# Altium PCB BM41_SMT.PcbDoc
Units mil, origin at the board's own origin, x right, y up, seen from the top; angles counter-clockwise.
Board outline 6000 x 4000 mil, 2 copper layers (Top, Bottom), stack 12.7 mil thick; 2 components, 0 nets, 32 pads, 0 vias.
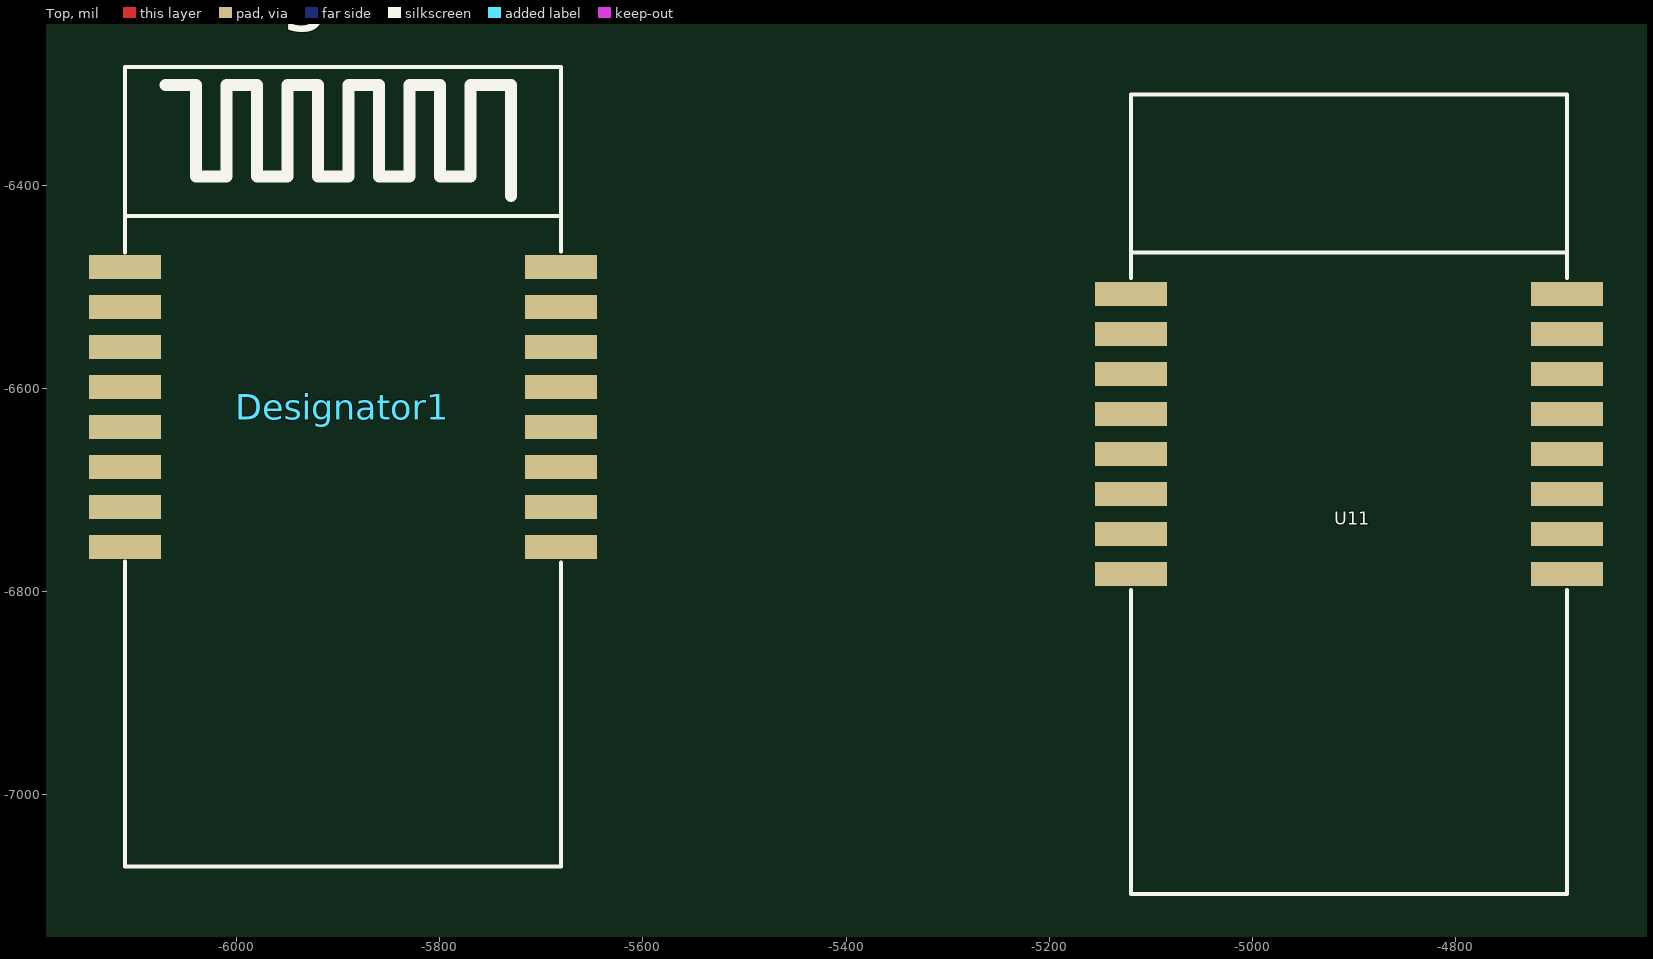
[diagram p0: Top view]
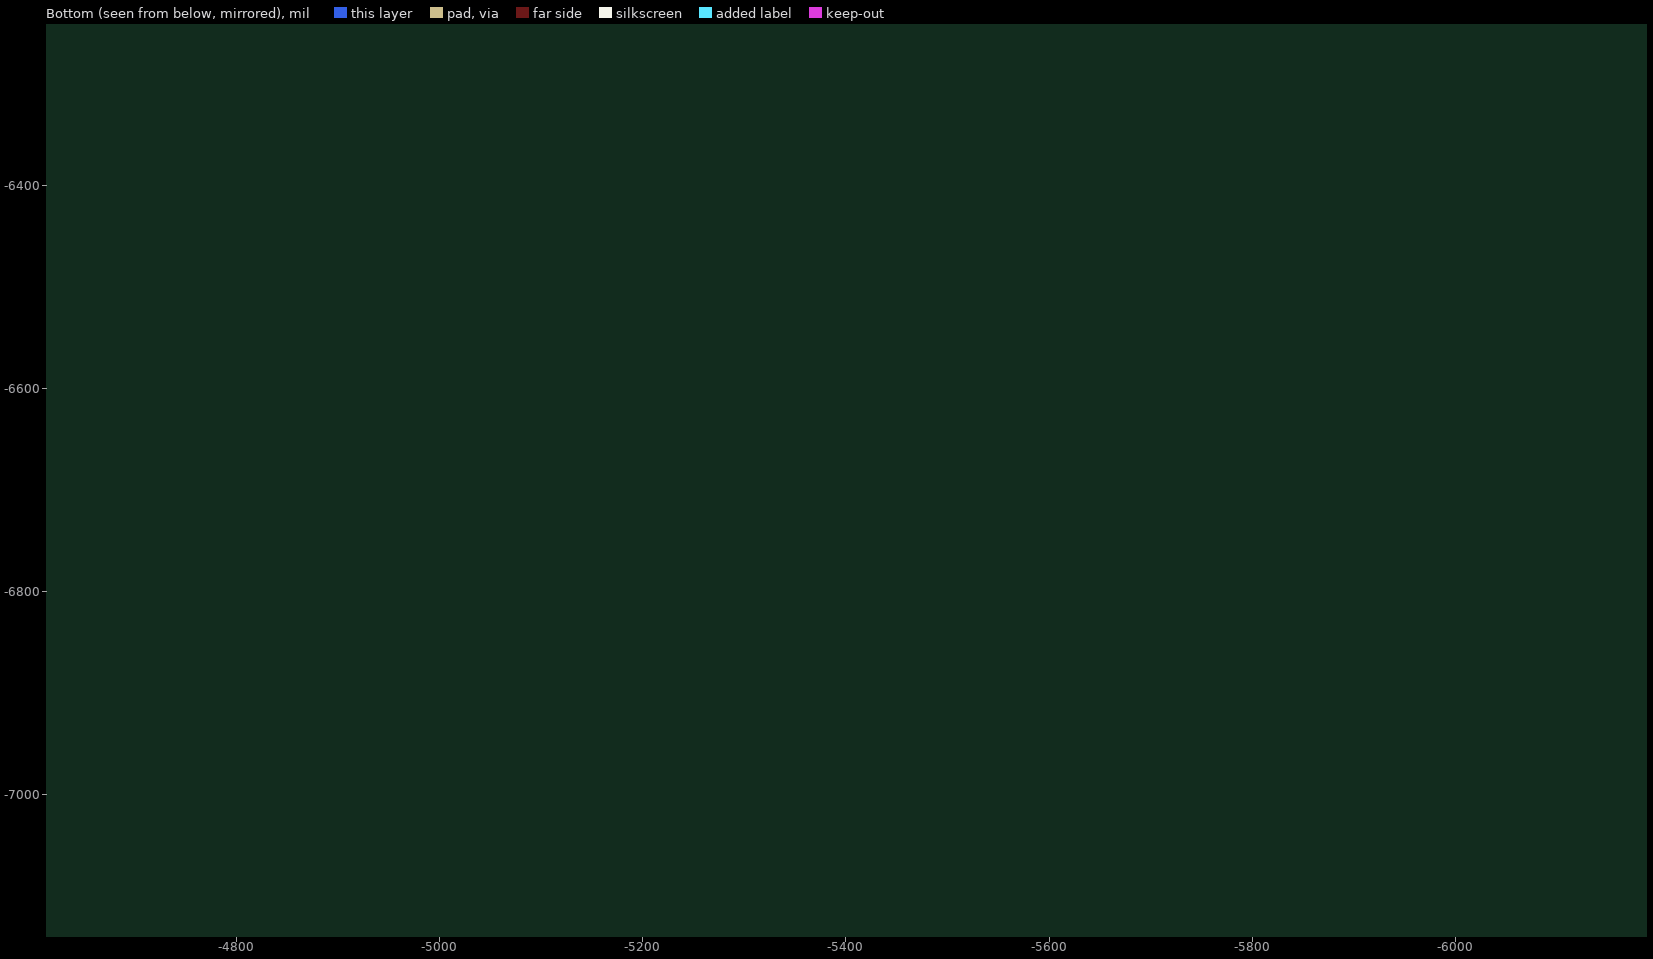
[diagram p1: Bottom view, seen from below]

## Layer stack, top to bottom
Solder Mask Top: solder mask 0.4, Solder Resist, Dk 3.5
Top: signal copper 1.35
Dielectric 1: dielectric 10, FR-4, Dk 4.3
Bottom: signal copper 1.35
Solder Mask Bottom: solder mask 0.4, Solder Resist, Dk 3.5

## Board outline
-9000,-9000 -3000,-9000 -3000,-5000 -9000,-5000

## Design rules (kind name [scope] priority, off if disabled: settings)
Clearance "Clearance - Default - DEFAULT- SMD" [IsVia vs IsSMTPin] p1: gap=6 ignorepadtopadclearanceinfootprint=FALSE
Clearance "Clearance - Default - DEFAULT - Via" [IsVia vs IsVia] p2: gap=6 ignorepadtopadclearanceinfootprint=FALSE
Clearance "Clearance - Default - DEFAULT - Net" [All] p3: gap=6 ignorepadtopadclearanceinfootprint=FALSE except(0: Arc-Hole Track-Hole SMDPad-Hole THPad-Hole Via-Hole Fill-Hole Poly-Hole Region-Hole Text-Hole; 10: Text-Text)
ComponentClearance "ComponentClearance - Default - DEFAULT" [All] p1: gap=6 collisioncheckmode=3 verticalgap=10 showdistances=FALSE
FanoutControl Fanout_Small [(CompPinCount < 5)] p3: bgadir=Out bgaviamode=Centered fanoutstyle=Auto fanoutdirection=OutThenIn viagrid=1 // Fanout_Small (Default Rule)
FanoutControl Fanout_SOIC [IsSOIC] p4: bgadir=Out bgaviamode=Centered fanoutstyle=Auto fanoutdirection=Alternating viagrid=1 // Fanout_SOIC (Default Rule)
HoleToHoleClearance "HoleToHoleClearance - Default - DEFAULT" [All] p1: gap=6 allowstackedmicrovias=TRUE
Length "Default Length" [All] p1: maxlimit=50000 minlimit=0
MaxMinImpedance "Default Impedance" [All] p1: minimum=50.00 maximum=150.0
ParallelSegment "Default Parallel Segment Adjasent" [All] p1: limit=1000 gap=200
ParallelSegment "Default Parallel Segment Same Layer" [All] p2: limit=1000 gap=200
PlaneConnect "Default PlaneConnect" [All] p1: planeconnectstyle=Relief reliefexpansion=20 reliefentries=4 reliefconductorwidth=15 reliefairgap=10
PolygonConnect "PolygonConnect - Default SMT" [IsSMTPin] p1: connectstyle=Relief reliefconductorwidth=10 reliefentries=4 polygonreliefangle="45 Angle" airgapwidth=10
PolygonConnect "PolygonConnect - Default Pad" [All] p2: connectstyle=Relief reliefconductorwidth=15 reliefentries=4 polygonreliefangle="45 Angle" airgapwidth=10
RoutingLayers "RoutingLayers - Default - DEFAULT" [All] p1: top layer_v5=TRUE bottom layer_v5=TRUE
RoutingPriority "RoutingPriority - Default - DEFAULT" [All] p1: routingpriority=3
RoutingTopology "Default Routing Topology" [All] p1: topology=Shortest
RoutingVias "RoutingVias - Default - DEFAULT" [All] p1: holewidth=37 width=55 viastyle="Through Hole" minholewidth=37 minwidth=55 maxholewidth=37 maxwidth=55
SMDToCorner "SMDToCorner - Default - DEFAULT" [All] p1: distance=60000
SolderMaskExpansion [All] p1: expansion=4 istentingtop=FALSE
Width "Default Width" [All] p1: maxlimit=12 minlimit=12 preferedwidth=12
22 further rules are at their usual default settings.

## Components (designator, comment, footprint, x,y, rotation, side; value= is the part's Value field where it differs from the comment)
Designator1 "Comment" BM41 -6110,-6480 r0 top
U11 "BM05_SMT" BM05_SMT -5119.13,-6833.66 r0 top

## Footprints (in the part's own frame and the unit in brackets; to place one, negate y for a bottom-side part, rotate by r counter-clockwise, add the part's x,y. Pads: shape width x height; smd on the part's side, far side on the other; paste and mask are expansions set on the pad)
BM05_SMT [mm]
  rect 1.8x0.6 smd: 1(10.9,1.3) 2(10.9,2.3) 3(10.9,3.3) 4(10.9,4.3) 5(10.9,5.3) 6(10.9,6.3) 7(10.9,7.3) 8(10.9,8.3) 9(0,8.3) 10(0,7.3) 11(0,6.3) 12(0,5.3) 13(0,4.3) 14(0,3.3) 15(0,2.3) 16(0,1.3)
  silkscreen extent 0,-6.7 13.95,13.3
BM41 [mm] "易联蓝牙模块"
  rect 1.8x0.6 smd: 1(10.9,-7) 2(10.9,-6) 3(10.9,-5) 4(10.9,-4) 5(10.9,-3) 6(10.9,-2) 7(10.9,-1) 8(10.9,0) 9(0,0) 10(0,-1) 11(0,-2) 12(0,-3) 13(0,-4) 14(0,-5) 15(0,-6) 16(0,-7)
  silkscreen extent 0,-15 10.9,5

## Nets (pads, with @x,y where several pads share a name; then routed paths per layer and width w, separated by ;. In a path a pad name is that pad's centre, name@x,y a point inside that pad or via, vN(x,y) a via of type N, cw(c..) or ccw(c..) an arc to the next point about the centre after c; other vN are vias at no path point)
pads on no net: Designator1.1 Designator1.2 Designator1.3 Designator1.4 Designator1.5 Designator1.6 Designator1.7 Designator1.8 Designator1.9 Designator1.10 Designator1.11 Designator1.12 Designator1.13 Designator1.14 Designator1.15 Designator1.16 U11.1 U11.2 U11.3 U11.4 U11.5 U11.6 U11.7 U11.8 U11.9 U11.10 U11.11 U11.12 U11.13 U11.14 U11.15 U11.16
